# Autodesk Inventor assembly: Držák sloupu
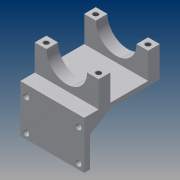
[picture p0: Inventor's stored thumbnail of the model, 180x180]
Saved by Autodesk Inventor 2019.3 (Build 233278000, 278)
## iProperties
Created: 2019-03
Part Number: Držák sloupu
Material: Všeobecné
Document SubType Name: Assembly
Designer: B-hon
Author: B-hon
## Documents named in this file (5)
- C:\Users\B-hon\OneDrive\Plocha\Bakalářka22\Držák sloupu.iam
- C:\Users\B-hon\OneDrive\Plocha\Bakalářka22\Deska upínací.ipt
- C:\Users\B-hon\OneDrive\Plocha\Bakalářka22\Základ upínací.ipt
- C:\Users\B-hon\OneDrive\Plocha\Bakalářka22\Výztuha.ipt
- C:\Users\B-hon\OneDrive\Plocha\Bakalářka22\Úchyt sloupu1.ipt
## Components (6 placed, 4 different names)
1. Deska upínací:1 — Proti sobě:1, Stejný směr:1, Proti sobě:2, Proti sobě:4, Stejný směr:4, Stejný směr:5, Stejný směr:6
2. Základ upínací:1 — Proti sobě:1, Stejný směr:1, Proti sobě:3, Stejný směr:3, Stejný směr:6
3. Výztuha:1 — Proti sobě:2, Proti sobě:3, Stejný směr:3
4. Výztuha:2
5. Úchyt sloupu1:1 — Proti sobě:4, Stejný směr:4, Stejný směr:5
6. Úchyt sloupu1:2
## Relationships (9: Flush 5, Mate 4)
- Proti sobě:1 [Mate]: Deska upínací:1 ↔ Základ upínací:1
- Stejný směr:1 [Flush]: Deska upínací:1 ↔ Základ upínací:1
- Proti sobě:2 [Mate]: Deska upínací:1 ↔ Výztuha:1
- Proti sobě:3 [Mate]: Základ upínací:1 ↔ Výztuha:1
- Stejný směr:3 [Flush]: Základ upínací:1 ↔ Výztuha:1
- Proti sobě:4 [Mate]: Deska upínací:1 ↔ Úchyt sloupu1:1
- Stejný směr:4 [Flush]: Deska upínací:1 ↔ Úchyt sloupu1:1
- Stejný směr:5 [Flush]: Deska upínací:1 ↔ Úchyt sloupu1:1
- Stejný směr:6 [Flush]: Deska upínací:1 ↔ Základ upínací:1
